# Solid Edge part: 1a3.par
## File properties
Author: edge
Template: jis part.par
Last saved by: edge
Revision: 22
Application: Solid Edge
Accuracy: 0.990
文書内容のタイプ: 0
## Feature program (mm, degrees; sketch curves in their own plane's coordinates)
sketch for "unnamed Protrusion 1" plane through (0, 0, 0) normal (1, 0, 0) x-axis (0, 1, 0)
  line (0, 0) -> (-80, 0)
  line (-80, 0) -> (-80, 180)
  line (-80, 180) -> (0, 180)
  line (0, 180) -> (0, 0)
extrude "unnamed Protrusion 1" add finite 160 symmetric
thinwall "Thinwall_1"  Thickness = 20 mm
sketch for "unnamed Cutout 1" plane through (0, 0, 0) normal (0, -1, 0) x-axis (1, 0, 0)
  circle centre (0, 120) radius 27.5
extrude "unnamed Cutout 1" cut through
sketch for "unnamed Cutout 2" #1 plane through (0, 0, 0) normal (0, -1, 0) x-axis (1, 0, 0)
sketch for "unnamed Cutout 2" #2 plane through (0, 0, 0) normal (0, -1, 0) x-axis (1, 0, 0)
  circle centre (-50, 120) radius 6
extrude "unnamed Cutout 2" cut through along +normal
sketch for "unnamed Cutout 3" #1 plane through (0, 0, 0) normal (0, 0, 1) x-axis (1, 0, 0)
sketch for "unnamed Cutout 3" #2 plane through (0, 0, 0) normal (0, 0, 1) x-axis (1, 0, 0)
extrude "unnamed Cutout 3" cut through along +normal
chamfer "Chamfer_1" setback 5
chamfer "Chamfer_2" setback 5
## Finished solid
Body 1: solid body, 17 faces, 40 edges, 20 vertices.
  Faces by surface: plane 12, cylinder 5
  Edges by curve: line 30, circle 10
Bounding box of the edges (mm): 160.000 x 80.000 x 180.000, from (-80, -80, 0) to (80, 0, 180).
Cylindrical faces by radius (mm): R6 x2, R7.5 x2, R27.5 x1
Planar faces by outward normal: +x 1, +y 1, +z 2, -x 1, -y 2, -z 1, oblique 4
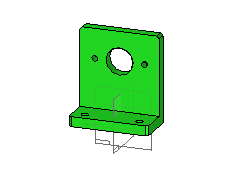
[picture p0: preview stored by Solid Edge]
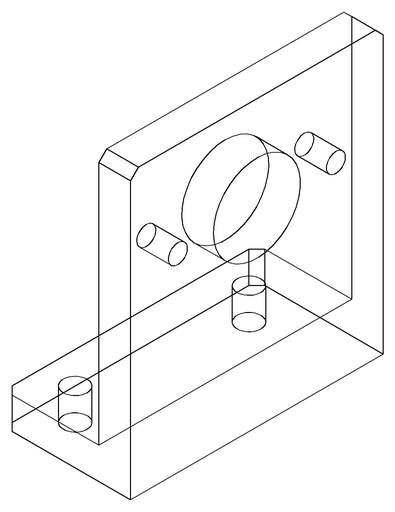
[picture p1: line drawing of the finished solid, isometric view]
